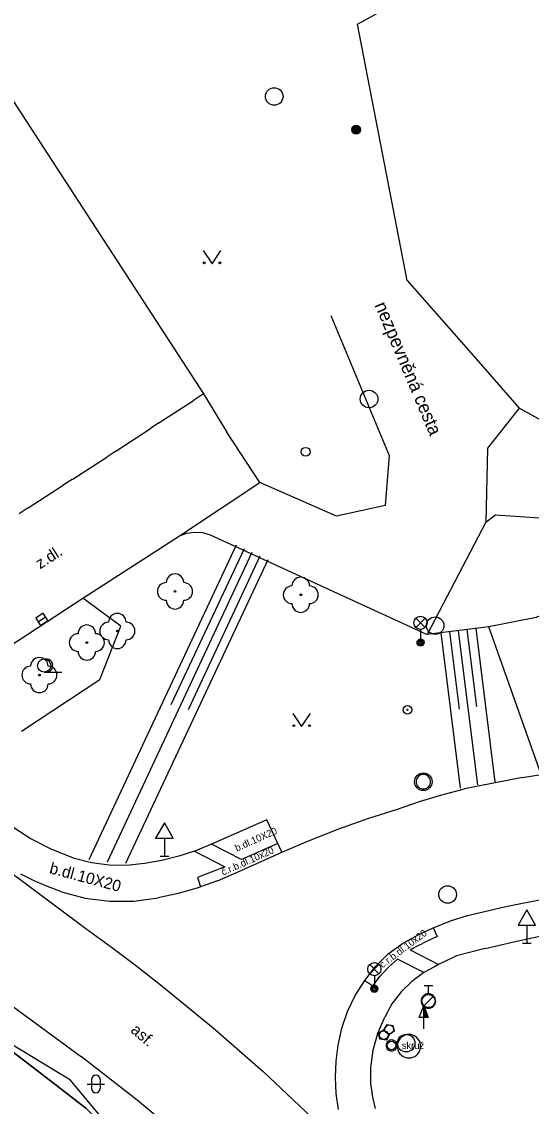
# Model space of a CAD drawing. Extents: x -598233 to -596890, y -1157848 to -1156431.
# Drawn here: x -598029.2 to -598000.2, y -1156812.1 to -1156750.3 of the extents above; entities that cross this region are included whole.
import ezdxf

# ---------------------------------------------------------------- set-up
doc = ezdxf.new("R2010")
doc.units = 0
for name, color, linetype in [('Level 10', 7, 'Continuous'), ('Level 11', 7, 'Continuous'), ('Level 14', 7, 'Continuous'), ('Level 15', 7, 'Continuous'), ('Level 21', 7, 'Continuous'), ('Level 22', 7, 'Continuous'), ('Level 23', 7, 'Continuous'), ('Level 25', 7, 'Continuous'), ('Level 27', 7, 'Continuous'), ('Level 28', 7, 'Continuous'), ('Level 33', 7, 'Continuous'), ('Level 34', 7, 'Continuous'), ('Level 36', 7, 'Continuous'), ('Level 40', 7, 'Continuous'), ('Level 42', 7, 'Continuous'), ('Level 5', 7, 'Continuous'), ('Level 6', 7, 'Continuous'), ('Vrstva 54', 7, 'Continuous'), ('Vrstva 60', 7, 'Continuous')]:
    doc.layers.add(name, color=color, linetype=linetype)

msp = doc.modelspace()

# ---------------------------------------------------------------- linework, layer by layer
at = {"layer": 'Level 10'}
for points in [[(-598015.69, -1156776.55), (-598017.56, -1156773.68)], [(-598020.27, -1156779.59), (-598015.69, -1156776.55)], [(-598025.76, -1156783.14), (-598020.27, -1156779.59)], [(-598032.66, -1156787.63), (-598025.76, -1156783.14)], [(-598000.74, -1156793.34), (-597999.67, -1156793.17), (-597997.42, -1156792.82), (-597995.65, -1156792.61), (-597994.77, -1156792.51), (-597994.08, -1156792.43)], [(-598000.74, -1156793.34), (-598004.04, -1156793.99)], [(-598007.86, -1156795.15), (-598006.6, -1156794.71), (-598005.33, -1156794.32), (-598004.04, -1156793.99)], [(-598014.44, -1156797.59), (-598012.83, -1156796.9), (-598011.19, -1156796.26), (-598009.54, -1156795.68), (-598007.86, -1156795.15)], [(-598042.84, -1156796.77), (-598025.84, -1156809.24)], [(-598018.1, -1156799.22), (-598016.88, -1156798.68), (-598015.66, -1156798.14), (-598014.44, -1156797.59)], [(-598026.98, -1156799.85), (-598027.77, -1156799.55), (-598028.54, -1156799.22), (-598029.3, -1156798.85)], [(-598018.1, -1156799.22), (-598019.06, -1156799.57), (-598019.2, -1156799.62), (-598020.33, -1156799.94), (-598021.48, -1156800.18)], [(-598026.98, -1156799.85), (-598025.63, -1156800.2), (-598024.25, -1156800.38), (-598022.86, -1156800.37), (-598021.48, -1156800.18)], [(-598003.87, -1156801.19), (-598001.69, -1156800.69), (-597999.49, -1156800.25), (-597997.29, -1156799.87), (-597995.07, -1156799.55)], [(-598006.68, -1156802.29), (-598005.82, -1156801.89), (-598005.77, -1156801.87), (-598004.83, -1156801.5)], [(-598004.83, -1156801.5), (-598003.87, -1156801.19)], [(-598009.71, -1156804.9), (-598009.1, -1156804.1), (-598008.38, -1156803.38), (-598007.57, -1156802.78), (-598006.68, -1156802.29)], [(-598010.26, -1156805.74), (-598009.71, -1156804.9)], [(-598010.69, -1156806.65), (-598010.26, -1156805.74)], [(-598011.22, -1156808.58), (-598011.02, -1156807.6), (-598010.69, -1156806.65)], [(-598011.34, -1156811.33), (-598011.38, -1156810.41), (-598011.34, -1156809.49), (-598011.22, -1156808.58)], [(-598022.68, -1156811.71), (-598025.84, -1156809.24)], [(-598011.21, -1156812.24), (-598011.34, -1156811.33)], [(-598020.63, -1156813.41), (-598022.68, -1156811.71)]]:
    msp.add_lwpolyline(points, dxfattribs=at)
at = {"layer": 'Level 11'}
for points in [[(-598007.3, -1156765.06), (-598010.13, -1156750.47), (-598006.24, -1156748.31), (-598007.77, -1156740.34), (-598009.22, -1156739.62), (-598009.53, -1156735.58), (-598010.2, -1156730.83)], [(-598007.3, -1156765.06), (-598003.52, -1156769.34), (-598000.93, -1156772.32), (-598002.72, -1156774.59), (-598002.82, -1156778.8), (-598006.17, -1156785.21)], [(-598011.65, -1156767.04), (-598008.33, -1156775.02), (-598008.56, -1156777.85), (-598011.32, -1156778.46), (-598015.69, -1156776.55)], [(-598018.89, -1156771.51), (-598017.56, -1156773.68)], [(-597993.45, -1156776.46), (-598000.93, -1156772.32)], [(-598002.82, -1156778.8), (-598002.27, -1156778.4), (-597998.93, -1156778.62), (-597992.22, -1156780.77)], [(-598020.27, -1156779.59), (-598019.85, -1156779.44), (-598019.4, -1156779.38), (-598018.95, -1156779.4), (-598018.52, -1156779.52)], [(-598018.52, -1156779.52), (-598006.17, -1156785.21)], [(-598005.9677, -1156793.58), (-598005.974, -1156793.5084), (-598005.9926, -1156793.439), (-598006.0229, -1156793.3738), (-598006.0642, -1156793.315), (-598006.115, -1156793.2642), (-598006.1738, -1156793.2229), (-598006.239, -1156793.1926), (-598006.3084, -1156793.174), (-598006.38, -1156793.1677), (-598006.4516, -1156793.174), (-598006.521, -1156793.1926), (-598006.5861, -1156793.2229), (-598006.645, -1156793.2642), (-598006.6958, -1156793.315), (-598006.7371, -1156793.3738), (-598006.7674, -1156793.439), (-598006.786, -1156793.5084), (-598006.7923, -1156793.58), (-598006.786, -1156793.6516), (-598006.7674, -1156793.721), (-598006.7371, -1156793.7861), (-598006.6958, -1156793.845), (-598006.645, -1156793.8958), (-598006.5861, -1156793.9371), (-598006.521, -1156793.9674), (-598006.4516, -1156793.986), (-598006.38, -1156793.9923), (-598006.3084, -1156793.986), (-598006.239, -1156793.9674), (-598006.1738, -1156793.9371), (-598006.115, -1156793.8958), (-598006.0642, -1156793.845), (-598006.0229, -1156793.7861), (-598005.9926, -1156793.721), (-598005.974, -1156793.6516), (-598005.9677, -1156793.58)], [(-598026.25, -1156797.95), (-598027.54, -1156797.44), (-598028.77, -1156796.81), (-598029.93, -1156796.05), (-598031.01, -1156795.18)], [(-598033.56, -1156796), (-598025.59, -1156801.93)], [(-598015.3, -1156795.75), (-598018.44, -1156797.14)], [(-598014.44, -1156797.59), (-598014.67, -1156797.1), (-598015.3, -1156795.75)], [(-598018.44, -1156797.14), (-598019.36, -1156797.51), (-598019.41, -1156797.53), (-598020.31, -1156797.82), (-598021.27, -1156798.06), (-598022.25, -1156798.24)], [(-598016.74, -1156798.01), (-598018.44, -1156797.14)], [(-598014.67, -1156797.1), (-598016.74, -1156798.01)], [(-598022.25, -1156798.24), (-598023.26, -1156798.35), (-598024.27, -1156798.33), (-598025.27, -1156798.2), (-598026.25, -1156797.95)], [(-598019.41, -1156797.53), (-598017.69, -1156798.43)], [(-598017.69, -1156798.43), (-598019.23, -1156799.04)], [(-598019.23, -1156799.04), (-598019.06, -1156799.57)], [(-598025.59, -1156801.93), (-598024.13, -1156802.99), (-598022.69, -1156804.08), (-598021.27, -1156805.19)], [(-598005.82, -1156801.89), (-598005.6, -1156802.39)], [(-598002.86, -1156803.07), (-598001.22, -1156802.69), (-597999.57, -1156802.33)], [(-598007.13, -1156803.15), (-598006.91, -1156803.02), (-598006.68, -1156802.9), (-598006.43, -1156802.78)], [(-598005.6, -1156802.39), (-598005.88, -1156802.52), (-598006.16, -1156802.65), (-598006.43, -1156802.78)], [(-598007.13, -1156803.15), (-598005.51, -1156803.99)], [(-598004.49, -1156803.49), (-598005.12, -1156803.79)], [(-598002.86, -1156803.07), (-598004.49, -1156803.49)], [(-598009.25, -1156805.2), (-598008.84, -1156804.64), (-598008.37, -1156804.13), (-598007.86, -1156803.67)], [(-598006.35, -1156804.44), (-598007.86, -1156803.67)], [(-598005.74, -1156804.11), (-598006.35, -1156804.44)], [(-598005.12, -1156803.79), (-598005.51, -1156803.99), (-598005.74, -1156804.11)], [(-598006.35, -1156804.44), (-598007.04, -1156804.95)], [(-598021.27, -1156805.19), (-598018.34, -1156807.58), (-598015.49, -1156810.07), (-598012.74, -1156812.67), (-598010.08, -1156815.36)], [(-598009.71, -1156804.9), (-598009.25, -1156805.2)], [(-598007.04, -1156804.95), (-598007.65, -1156805.54)], [(-598007.65, -1156805.54), (-598008.17, -1156806.22)], [(-598005.6777, -1156806.06), (-598005.684, -1156805.9884), (-598005.7026, -1156805.919), (-598005.7329, -1156805.8538), (-598005.7742, -1156805.795), (-598005.825, -1156805.7442), (-598005.8838, -1156805.7029), (-598005.949, -1156805.6726), (-598006.0184, -1156805.654), (-598006.09, -1156805.6477), (-598006.1616, -1156805.654), (-598006.231, -1156805.6726), (-598006.2961, -1156805.7029), (-598006.355, -1156805.7442), (-598006.4058, -1156805.795), (-598006.4471, -1156805.8538), (-598006.4774, -1156805.919), (-598006.496, -1156805.9884), (-598006.5023, -1156806.06), (-598006.496, -1156806.1316), (-598006.4774, -1156806.201), (-598006.4471, -1156806.2661), (-598006.4058, -1156806.325), (-598006.355, -1156806.3758), (-598006.2961, -1156806.4171), (-598006.231, -1156806.4474), (-598006.1616, -1156806.466), (-598006.09, -1156806.4723), (-598006.0184, -1156806.466), (-598005.949, -1156806.4474), (-598005.8838, -1156806.4171), (-598005.825, -1156806.3758), (-598005.7742, -1156806.325), (-598005.7329, -1156806.2661), (-598005.7026, -1156806.201), (-598005.684, -1156806.1316), (-598005.6777, -1156806.06)], [(-598008.17, -1156806.22), (-598008.58, -1156806.97)], [(-598009.37, -1156810.86), (-598009.37, -1156809.86), (-598009.24, -1156808.86), (-598008.97, -1156807.89), (-598008.58, -1156806.97)], [(-598008.31, -1156807.96), (-598008.48, -1156808.29), (-598008.85, -1156808.24), (-598008.93, -1156807.87), (-598008.61, -1156807.68)], [(-598008.61, -1156807.68), (-598008.44, -1156807.4), (-598008.12, -1156807.46), (-598008.05, -1156807.77), (-598008.31, -1156807.96)], [(-598007.8762, -1156808.59), (-598007.881, -1156808.5355), (-598007.8951, -1156808.4827), (-598007.9182, -1156808.4331), (-598007.9496, -1156808.3883), (-598007.9883, -1156808.3496), (-598008.0331, -1156808.3182), (-598008.0827, -1156808.2951), (-598008.1355, -1156808.281), (-598008.19, -1156808.2762), (-598008.2445, -1156808.281), (-598008.2973, -1156808.2951), (-598008.3469, -1156808.3182), (-598008.3917, -1156808.3496), (-598008.4304, -1156808.3883), (-598008.4618, -1156808.4331), (-598008.4849, -1156808.4827), (-598008.499, -1156808.5355), (-598008.5038, -1156808.59), (-598008.499, -1156808.6445), (-598008.4849, -1156808.6973), (-598008.4618, -1156808.7469), (-598008.4304, -1156808.7917), (-598008.3917, -1156808.8304), (-598008.3469, -1156808.8618), (-598008.2973, -1156808.8849), (-598008.2445, -1156808.899), (-598008.19, -1156808.9038), (-598008.1355, -1156808.899), (-598008.0827, -1156808.8849), (-598008.0331, -1156808.8618), (-598007.9883, -1156808.8304), (-598007.9496, -1156808.7917), (-598007.9182, -1156808.7469), (-598007.8951, -1156808.6973), (-598007.881, -1156808.6445), (-598007.8762, -1156808.59)], [(-598006.5343, -1156808.6315), (-598006.5444, -1156808.5158), (-598006.5745, -1156808.4036), (-598006.6236, -1156808.2983), (-598006.6902, -1156808.2031), (-598006.7724, -1156808.121), (-598006.8675, -1156808.0543), (-598006.9728, -1156808.0052), (-598007.085, -1156807.9751), (-598007.2008, -1156807.965), (-598007.3165, -1156807.9751), (-598007.4287, -1156808.0052), (-598007.534, -1156808.0543), (-598007.6292, -1156808.1209), (-598007.7113, -1156808.2031), (-598007.778, -1156808.2983), (-598007.8271, -1156808.4035), (-598007.8571, -1156808.5158), (-598007.8672, -1156808.6315), (-598007.8571, -1156808.7472), (-598007.8271, -1156808.8594), (-598007.778, -1156808.9647), (-598007.7113, -1156809.0599), (-598007.6292, -1156809.142), (-598007.534, -1156809.2087), (-598007.4287, -1156809.2578), (-598007.3165, -1156809.2878), (-598007.2008, -1156809.298), (-598007.085, -1156809.2878), (-598006.9728, -1156809.2578), (-598006.8675, -1156809.2087), (-598006.7724, -1156809.142), (-598006.6902, -1156809.0599), (-598006.6236, -1156808.9647), (-598006.5745, -1156808.8594), (-598006.5444, -1156808.7472), (-598006.5343, -1156808.6315)], [(-598009.37, -1156810.86), (-598009.27, -1156811.53)], [(-598009.27, -1156811.53), (-598009.13, -1156812.18)]]:
    msp.add_lwpolyline(points, dxfattribs=at)
at = {"layer": 'Level 14'}
msp.add_lwpolyline([(-598002.66, -1156784.77), (-598006.17, -1156785.21)], dxfattribs=at)
at = {"layer": 'Level 15'}
for points in [[(-598017.04, -1156780.11), (-598025.43, -1156798.02)], [(-598016.14, -1156780.54), (-598024.39, -1156798.15)], [(-598016.59, -1156780.33), (-598020.75, -1156789.2)], [(-598015.68, -1156780.75), (-598019.77, -1156789.48)], [(-598015.23, -1156780.96), (-598023.33, -1156798.24)], [(-598004.89, -1156785.05), (-598004.34, -1156789.45)], [(-598004.39, -1156784.99), (-598003.29, -1156793.75)], [(-598003.9, -1156784.92), (-598003.35, -1156789.29)], [(-598003.4, -1156784.86), (-598002.31, -1156793.58)], [(-598005.38, -1156785.11), (-598004.28, -1156793.94)]]:
    msp.add_lwpolyline(points, dxfattribs=at)
at = {"layer": 'Level 21'}
for points in [[(-598023.6, -1156784.73), (-598025.76, -1156783.14)], [(-598024.79, -1156787.76), (-598023.6, -1156784.73)], [(-598029.26, -1156790.71), (-598024.79, -1156787.76)], [(-598026.46, -1156810.56), (-598031.36, -1156807.6)], [(-598023.93, -1156813.61), (-598026.46, -1156810.56)]]:
    msp.add_lwpolyline(points, dxfattribs=at)
at = {"layer": 'Level 22'}
for centre in [(-598020.52, -1156782.75), (-598013.36, -1156782.94), (-598023.8, -1156785), (-598025.54, -1156785.66), (-598028.24, -1156787.51)]:
    msp.add_circle(centre, 0.05, dxfattribs=at)
for centre, start, end in [((-598020.52, -1156782.25), 0, 180), ((-598013.36, -1156782.44), 0, 180), ((-598021.02, -1156782.75), 90, 270), ((-598020.02, -1156782.75), 270, 90), ((-598013.86, -1156782.94), 90, 270), ((-598012.86, -1156782.94), 270, 90), ((-598020.52, -1156783.25), 180, 0), ((-598013.36, -1156783.44), 180, 0), ((-598023.8, -1156784.5), 0, 180), ((-598025.54, -1156785.16), 0, 180), ((-598024.3, -1156785), 90, 270), ((-598023.3, -1156785), 270, 90), ((-598026.04, -1156785.66), 90, 270), ((-598025.04, -1156785.66), 270, 90), ((-598023.8, -1156785.5), 180, 0), ((-598025.54, -1156786.16), 180, 0), ((-598028.24, -1156787.01), 0, 180), ((-598028.74, -1156787.51), 90, 270), ((-598027.74, -1156787.51), 270, 90), ((-598028.24, -1156788.01), 180, 0)]:
    msp.add_arc(centre, 0.5, start, end, dxfattribs=at)
at = {"layer": 'Level 23'}
for points in [[(-597996.05, -1156783.5), (-597997.54, -1156783.13), (-597999.95, -1156784.24), (-598002.66, -1156784.77)], [(-597999.67, -1156793.17), (-598002.66, -1156784.77)]]:
    msp.add_lwpolyline(points, dxfattribs=at)
at = {"layer": 'Level 25'}
for p, q in [((-598006.612, -1156806.998), (-598006.36, -1156806.324)), ((-598006.36, -1156806.998), (-598006.612, -1156806.998)), ((-598006.36, -1156807.65), (-598006.36, -1156807))]:
    msp.add_line(p, q, dxfattribs=at)
for points in [[(-598006.11, -1156807), (-598006.36, -1156807), (-598006.36, -1156806.324), (-598006.36, -1156806.324)], [(-598006.167, -1156806.96), (-598006.32, -1156806.96), (-598006.32, -1156806.547)], [(-598006.225, -1156806.92), (-598006.28, -1156806.92), (-598006.28, -1156806.771)]]:
    msp.add_lwpolyline(points, close=True, dxfattribs=at)
for centre, radius in [((-598010.2, -1156756.4699), 0.25), ((-598010.2, -1156756.4699), 0.2), ((-598010.2, -1156756.4699), 0.15), ((-598010.2, -1156756.4699), 0.1), ((-598010.2, -1156756.4699), 0.05), ((-598007.28, -1156789.49), 0.25), ((-598007.28, -1156789.49), 0.0303)]:
    msp.add_circle(centre, radius, dxfattribs=at)
at = {"layer": 'Level 27'}
msp.add_line((-598028.3083, -1156784.4783), (-598027.8917, -1156784.2017), dxfattribs=at)
msp.add_lwpolyline([(-598028.17, -1156784.6866), (-598027.7534, -1156784.41), (-598028.03, -1156783.9934), (-598028.4466, -1156784.27)], close=True, dxfattribs=at)
for centre in [(-598014.87, -1156754.58), (-598009.47, -1156771.8), (-598005.71, -1156784.7), (-598006.38, -1156793.58), (-598005, -1156800), (-598007.36, -1156808.46)]:
    msp.add_circle(centre, 0.5, dxfattribs=at)
at = {"layer": 'Level 28'}
for p, q in [((-598006.34, -1156805.185), (-598005.84, -1156805.185)), ((-598006.09, -1156805.685), (-598006.09, -1156805.185)), ((-598006.348, -1156806.332), (-598005.818, -1156805.802))]:
    msp.add_line(p, q, dxfattribs=at)
for centre, radius in [((-598013.08, -1156774.8), 0.25), ((-598006.09, -1156806.06), 0.375), ((-598008.63, -1156808), 0.25), ((-598008.32, -1156807.67), 0.25), ((-598008.19, -1156808.59), 0.25)]:
    msp.add_circle(centre, radius, dxfattribs=at)
at = {"layer": 'Level 33'}
for p, q in [((-598006.805, -1156784.8), (-598006.275, -1156784.27)), ((-598006.805, -1156784.27), (-598006.275, -1156784.8)), ((-598006.54, -1156784.91), (-598006.54, -1156785.66)), ((-598009.435, -1156804.51), (-598008.905, -1156803.98)), ((-598009.435, -1156803.98), (-598008.905, -1156804.51)), ((-598009.17, -1156804.62), (-598009.17, -1156805.37))]:
    msp.add_line(p, q, dxfattribs=at)
for centre, radius in [((-598006.54, -1156784.535), 0.375), ((-598006.54, -1156785.66), 0.2), ((-598006.54, -1156785.66), 0.1445), ((-598006.54, -1156785.66), 0.0876), ((-598009.17, -1156804.245), 0.375), ((-598009.17, -1156805.37), 0.2), ((-598009.17, -1156805.37), 0.1445), ((-598009.17, -1156805.37), 0.0876)]:
    msp.add_circle(centre, radius, dxfattribs=at)
at = {"layer": 'Level 34'}
for p, q in [((-598021.12, -1156796.792), (-598021.12, -1156797.81)), ((-598021.37, -1156797.81), (-598020.87, -1156797.81)), ((-598000.49, -1156801.742), (-598000.49, -1156802.76)), ((-598000.74, -1156802.76), (-598000.24, -1156802.76))]:
    msp.add_line(p, q, dxfattribs=at)
for points in [[(-598021.62, -1156796.792), (-598020.62, -1156796.792), (-598021.12, -1156795.926)], [(-598000.99, -1156801.742), (-597999.99, -1156801.742), (-598000.49, -1156800.876)]]:
    msp.add_lwpolyline(points, close=True, dxfattribs=at)
at = {"layer": 'Level 36'}
for p, q in [((-598027.97, -1156787.345), (-598026.97, -1156787.345)), ((-598025.526, -1156810.786), (-598024.526, -1156810.786)), ((-598025.276, -1156810.536), (-598025.276, -1156811.036)), ((-598024.776, -1156810.536), (-598024.776, -1156811.036))]:
    msp.add_line(p, q, dxfattribs=at)
for points in [[(-598018.91, -1156763.35), (-598018.41, -1156764.1), (-598017.91, -1156763.35)], [(-598013.81, -1156789.69), (-598013.31, -1156790.44), (-598012.81, -1156789.69)]]:
    msp.add_lwpolyline(points, dxfattribs=at)
for centre, radius in [((-598018.8602, -1156764.0498), 0.05), ((-598017.9608, -1156764.0498), 0.05), ((-598027.97, -1156786.9696), 0.375), ((-598013.7602, -1156790.3898), 0.05), ((-598012.8608, -1156790.3898), 0.05)]:
    msp.add_circle(centre, radius, dxfattribs=at)
for centre, radius, start, end in [((-598027.845, -1156786.9696), 0.375, 260.405931, 99.594069), ((-598025.0257, -1156810.5363), 0.25, 0, 180), ((-598025.0257, -1156811.0363), 0.25, 180, 0)]:
    msp.add_arc(centre, radius, start, end, dxfattribs=at)
at = {"layer": 'Level 5'}
for points in [[(-598033.96, -1156748.35), (-598030.76, -1156753.27), (-598029.72, -1156754.86), (-598018.89, -1156771.51)], [(-598021.43, -1156773.16), (-598019.46, -1156771.88)], [(-598018.89, -1156771.51), (-598019.46, -1156771.88)], [(-598021.43, -1156773.16), (-598021.92, -1156773.48)], [(-598023.89, -1156774.76), (-598021.92, -1156773.48)], [(-598026.38, -1156776.38), (-598024.4, -1156775.1)], [(-598023.89, -1156774.76), (-598024.4, -1156775.1)], [(-598026.38, -1156776.38), (-598026.88, -1156776.71)], [(-598028.87, -1156778), (-598026.88, -1156776.71)], [(-598028.87, -1156778), (-598029.39, -1156778.34)]]:
    msp.add_lwpolyline(points, dxfattribs=at)
at = {"layer": 'Level 6'}
for points in [[(-598021.43, -1156773.16), (-598019.46, -1156771.88)], [(-598023.89, -1156774.76), (-598021.92, -1156773.48)], [(-598026.38, -1156776.38), (-598024.4, -1156775.1)], [(-598028.87, -1156778), (-598026.88, -1156776.71)]]:
    msp.add_lwpolyline(points, dxfattribs=at)
at = {"layer": 'Vrstva 54'}
for p, q in [((-598033.02, -1156806.47), (-598027.61, -1156810.61)), ((-598027.61, -1156810.61), (-598025.6, -1156812.15))]:
    msp.add_line(p, q, dxfattribs=at)
at = {"layer": 'Vrstva 60'}
for points in [[(-598051.82, -1156669.27), (-598056.59, -1156696.84), (-598058.24, -1156716.84), (-598058.5, -1156719.61), (-598060.26, -1156738.45), (-598062.32, -1156767.72), (-598059.85, -1156780.87), (-598055.12, -1156786.5), (-598046.79, -1156796.42), (-598042.33, -1156799.68), (-598035.7, -1156804.52), (-598033.02, -1156806.47), (-598027.61, -1156810.61), (-598025.6, -1156812.15), (-598015.97, -1156821.78), (-598014.05, -1156825.16), (-598009.94, -1156832.4), (-598008.9, -1156844.6), (-598012.47, -1156871.86)], [(-598012.47, -1156871.86), (-598008.9, -1156844.6), (-598009.94, -1156832.4), (-598014.05, -1156825.16), (-598015.97, -1156821.78), (-598025.6, -1156812.15), (-598027.61, -1156810.61), (-598033.02, -1156806.47), (-598035.7, -1156804.52), (-598042.33, -1156799.68), (-598046.79, -1156796.42), (-598055.12, -1156786.5), (-598059.85, -1156780.87), (-598062.32, -1156767.72), (-598060.26, -1156738.45), (-598058.5, -1156719.61), (-598058.24, -1156716.84), (-598056.59, -1156696.84), (-598051.82, -1156669.27)]]:
    msp.add_lwpolyline(points, dxfattribs=at)

# ---------------------------------------------------------------- texts
at = {"layer": 'Level 40'}
for s, height, rotation, p in [('z.dl.', 0.65, 32.88793, (-598028.2, -1156781.5)), ('b.dl.10X20', 0.4, 24, (-598017, -1156797.56)), ('č.r.b.dl.10x20', 0.4, 24, (-598017.78, -1156798.93)), ('b.dl.10X20', 0.65, 345, (-598027.71, -1156798.78)), ('č.r.b.dl.10x20', 0.4, 37, (-598008.7, -1156804.21)), ('asf.', 0.65, 319.110942, (-598023.09, -1156807.79))]:
    msp.add_text(s, height=height, rotation=rotation, dxfattribs=at).set_placement(p)
at = {"layer": 'Level 42'}
msp.add_text('nezpevněná cesta', height=0.75, rotation=293, dxfattribs=at).set_placement((-598009.17, -1156766.45))
msp.add_text('skruž', height=0.4, dxfattribs=at).set_placement((-598007.61, -1156808.79))

doc.saveas('drawing.dxf')
